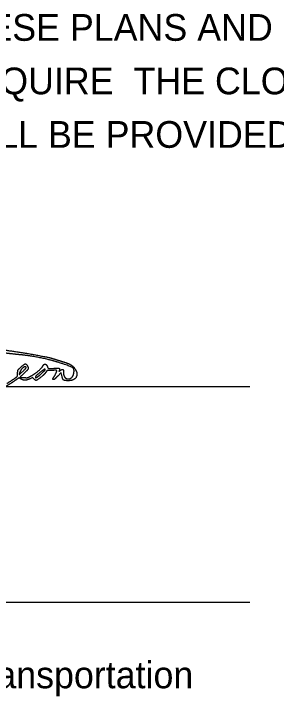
# Model space of a CAD drawing. Extents: x 0 to 34, y 0 to 22.
# Drawn here: x 26.793 to 28.167, y 7.305 to 10.877 of the extents above; entities that cross this region are included whole.
import ezdxf

# ---------------------------------------------------------------- set-up
doc = ezdxf.new("R2010")
doc.units = 0
doc.layers.add('SH_Data', color=7, linetype='Continuous')
doc.layers.add('SH_Text', color=7, linetype='Continuous')

msp = doc.modelspace()

# ---------------------------------------------------------------- linework, layer by layer
at = {"layer": 'SH_Data'}
for p, q in [((24.5279, 8.9262), (28.0279, 8.9262)), ((24.5279, 7.7968), (28.0279, 7.7968))]:
    msp.add_line(p, q, dxfattribs=at)
for points in [[(26.9932, 9.0105), (26.9682, 9.0101), (26.9603, 8.999)], [(26.8291, 8.9666), (26.8211, 8.9719), (26.8059, 8.9609)], [(26.8976, 8.9667), (26.8921, 8.9724), (26.8784, 8.9662)], [(27.0438, 8.9881), (27.0414, 8.9992), (27.0235, 8.9805)]]:
    msp.add_lwpolyline(points, dxfattribs=at)
for points in [[(26.4236, 9.1137), (26.5451, 9.1299), (26.7687, 9.1185), (26.9255, 9.088)], [(26.8282, 9.0919), (26.8116, 9.0935), (26.7715, 9.0978), (26.7391, 9.1015)], [(27.024, 9.0529), (26.9771, 9.0675), (26.8803, 9.0868), (26.8282, 9.0919)], [(26.9255, 9.088), (26.9757, 9.0783), (26.9906, 9.0747), (27.0154, 9.0667)], [(26.8336, 9.03), (26.8494, 9.0441), (26.8579, 9.0456), (26.864, 9.0353)], [(26.9462, 9.0339), (26.9521, 9.0453), (26.9665, 9.0406), (26.971, 9.0258)], [(27.0154, 9.0667), (27.0254, 9.0635), (27.0412, 9.0586), (27.0505, 9.0558)], [(27.1069, 8.9931), (27.1124, 9.0166), (27.0912, 9.0319), (27.024, 9.0529)], [(27.0505, 9.0558), (27.075, 9.0484), (27.1025, 9.0335), (27.1102, 9.0234)], [(26.8137, 8.992), (26.8136, 9.0081), (26.8176, 9.0157), (26.8336, 9.03)], [(26.8269, 9.0046), (26.8201, 8.989), (26.8248, 8.9897), (26.8426, 9.0069)], [(26.8521, 9.029), (26.8465, 9.0293), (26.8311, 9.0143), (26.8269, 9.0046)], [(26.8426, 9.0069), (26.8573, 9.0212), (26.8605, 9.0287), (26.8521, 9.029)], [(26.864, 9.0353), (26.8709, 9.0238), (26.8658, 9.0117), (26.8468, 8.9948)], [(26.8848, 8.9817), (26.9048, 8.9927), (26.9409, 9.0234), (26.9462, 9.0339)], [(26.955, 9.0166), (26.9541, 9.0167), (26.943, 9.0087), (26.9305, 8.999)], [(26.9378, 8.9932), (26.954, 9.0078), (26.9603, 9.0164), (26.955, 9.0166)], [(26.971, 9.0258), (26.9726, 9.0205), (26.9875, 9.0191), (27.0108, 9.022)], [(27.0188, 9.0102), (27.0184, 9.0106), (27.0069, 9.0107), (26.9932, 9.0105)], [(27.0037, 8.9761), (27.0081, 8.9823), (27.0199, 9.009), (27.0188, 9.0102)], [(27.0108, 9.022), (27.0262, 9.0239), (27.0344, 9.0189), (27.0311, 9.0098)], [(27.0311, 9.0098), (27.0293, 9.0048), (27.0294, 9.0048), (27.0366, 9.0099)], [(27.0366, 9.0099), (27.0462, 9.0168), (27.0539, 9.0131), (27.0534, 9.0018)], [(27.1102, 9.0234), (27.1313, 8.9961), (27.109, 8.9551), (27.0737, 8.9563)], [(26.758, 8.9428), (26.7697, 8.9492), (26.7991, 8.969), (26.8113, 8.9786)], [(26.8113, 8.9786), (26.8127, 8.9797), (26.8138, 8.9857), (26.8137, 8.992)], [(26.8468, 8.9948), (26.8271, 8.9773), (26.8279, 8.9735), (26.8516, 8.9724)], [(26.8516, 8.9724), (26.8646, 8.9719), (26.8691, 8.9731), (26.8848, 8.9817)], [(26.9383, 8.977), (26.9148, 8.9588), (26.9071, 8.9569), (26.8976, 8.9667)], [(26.9305, 8.999), (26.9165, 8.9881), (26.9076, 8.9793), (26.9074, 8.9762)], [(26.9074, 8.9762), (26.9073, 8.9718), (26.908, 8.9715), (26.9133, 8.9739)], [(26.9133, 8.9739), (26.9166, 8.9754), (26.9276, 8.9841), (26.9378, 8.9932)], [(26.9603, 8.999), (26.9559, 8.9929), (26.946, 8.983), (26.9383, 8.977)], [(27.0023, 8.9619), (26.9978, 8.9621), (26.9985, 8.9689), (27.0037, 8.9761)], [(27.0235, 8.9805), (27.0136, 8.9702), (27.0041, 8.9619), (27.0023, 8.9619)], [(27.0737, 8.9563), (27.0567, 8.9568), (27.0487, 8.9654), (27.0438, 8.9881)], [(27.0534, 9.0018), (27.0529, 8.991), (27.0597, 8.9729), (27.0655, 8.9695)], [(27.0655, 8.9695), (27.0785, 8.9618), (27.1028, 8.9756), (27.1069, 8.9931)], [(26.8059, 8.9609), (26.7976, 8.9548), (26.7697, 8.9371), (26.7439, 8.9214)], [(26.8784, 8.9662), (26.8615, 8.9585), (26.8408, 8.9587), (26.8291, 8.9666)]]:
    msp.add_open_spline(points, degree=2, dxfattribs=at)

# ---------------------------------------------------------------- texts
at = {"layer": 'SH_Text'}
for s, p in [('I HEREBY APPROVE THESE PLANS AND DECLARE THAT THE MAKING OF THIS', (24.5279, 10.735)), ('IMPROVEMENT WILL REQUIRE  THE CLOSING TO TRAFFIC OF THE HIGHWAY', (24.5279, 10.455)), ('AND THAT DETOURS WILL BE PROVIDED AS INDICATED ON SHEET 11.', (24.5279, 10.175)), ('Director, Department of Transportation', (24.5279, 7.3468))]:
    msp.add_text(s, height=0.14, dxfattribs=at).set_placement(p)

doc.saveas('drawing.dxf')
